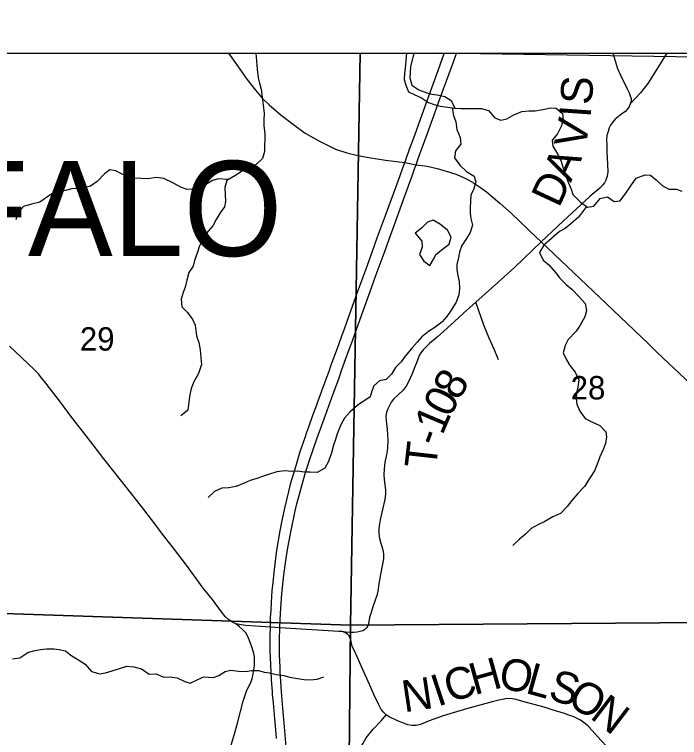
# Model space of a CAD drawing. Extents: x 0 to 34, y 0 to 22.
# Drawn here: x 6.166 to 7.359, y 16.857 to 18.153 of the extents above; entities that cross this region are included whole.
import ezdxf

# ---------------------------------------------------------------- set-up
doc = ezdxf.new("R2010")
doc.units = 0
for name, color, linetype in [('GM_X_Corporation', 7, 'Continuous'), ('GM_X_County_Road', 7, 'Continuous'), ('GM_X_County_Road_Text', 7, 'Continuous'), ('GM_X_Interstate_Route', 7, 'Continuous'), ('GM_X_Minor_Lake', 7, 'Continuous'), ('GM_X_Minor_River', 7, 'Continuous'), ('GM_X_Section_Text', 7, 'Continuous'), ('GM_X_State_Route', 7, 'Continuous'), ('GM_X_Township_Road', 7, 'Continuous'), ('GM_X_Township_Road_Text', 7, 'Continuous'), ('GM_X_Township_Text', 7, 'Continuous'), ('SH_Data', 7, 'Continuous')]:
    doc.layers.add(name, color=color, linetype=linetype)

msp = doc.modelspace()

# ---------------------------------------------------------------- linework, layer by layer
at = {"layer": 'GM_X_Corporation'}
for points in [[(6.7857, 18.0831), (6.7684, 17.0582), (5.7733, 17.0918), (5.7957, 18.0831)], [(7.8172, 18.0831), (7.7982, 17.0659), (6.7684, 17.0582), (6.7857, 18.0831)], [(7.8172, 18.0831), (7.817, 18.0695), (6.9241, 18.0832)]]:
    msp.add_lwpolyline(points, dxfattribs=at)
for points in [[(6.7684, 17.0582), (6.7585, 16.0372), (5.82, 16.0635), (5.7783, 16.0638), (5.7733, 17.0918)], [(7.7982, 17.0659), (7.8046, 16.0144), (6.8244, 16.0368), (6.7585, 16.0372), (6.7684, 17.0582)]]:
    msp.add_lwpolyline(points, close=True, dxfattribs=at)
at = {"layer": 'GM_X_County_Road'}
for points in [[(7.239, 18.0831), (7.2476, 18.0558), (7.2524, 18.0439), (7.2647, 18.0193), (7.268, 18.012), (7.2707, 18.0053), (7.2716, 18.002), (7.2719, 17.9975), (7.2703, 17.9924)], [(7.2703, 17.9924), (7.2683, 17.9874), (7.2654, 17.9836), (7.2614, 17.9791), (7.2548, 17.9744), (7.2493, 17.9701), (7.2432, 17.9649), (7.2383, 17.9593), (7.2347, 17.9541), (7.2324, 17.9493), (7.2304, 17.943), (7.2283, 17.9358), (7.2278, 17.9277), (7.2279, 17.9192), (7.2284, 17.9068), (7.2296, 17.8841), (7.2297, 17.871), (7.2285, 17.8629), (7.2266, 17.8558), (7.2239, 17.8507), (7.2205, 17.8466), (7.2156, 17.8413), (7.1985, 17.8271), (7.1501, 17.782), (7.1106, 17.7455)], [(6.7716, 17.0208), (6.7704, 17.0259), (6.7689, 17.0319), (6.7677, 17.0363), (6.7664, 17.0389), (6.764, 17.0416), (6.7596, 17.0447), (6.7534, 17.0466), (6.7478, 17.0471), (6.642, 17.0534), (6.6252, 17.0547), (6.5984, 17.0562), (6.5811, 17.0575), (6.5724, 17.0586), (6.5629, 17.0608), (6.5568, 17.0635), (6.5505, 17.0679), (6.5441, 17.0738), (6.5376, 17.0823), (6.5211, 17.1043), (6.5047, 17.1248), (6.4919, 17.142), (6.4746, 17.1659), (6.4533, 17.1936), (6.4338, 17.2183), (6.4116, 17.2479), (6.3978, 17.2657), (6.3855, 17.2818), (6.3449, 17.3328), (6.3261, 17.3566), (6.3075, 17.3814), (6.2672, 17.4331), (6.2448, 17.4624), (6.2345, 17.4763), (6.2225, 17.492), (6.2142, 17.5021), (6.209, 17.5084), (6.2015, 17.5167), (6.1575, 17.558)], [(6.5491, 16.8253), (6.5606, 16.8635), (6.5659, 16.8826), (6.5764, 16.9223), (6.5829, 16.9416), (6.5898, 16.9552), (6.5925, 16.9629), (6.5937, 16.9675), (6.5949, 16.9748), (6.5962, 16.9856), (6.5964, 16.9929), (6.5964, 17.0007), (6.5951, 17.0076), (6.5923, 17.0175), (6.5883, 17.0292), (6.5845, 17.0381), (6.5807, 17.0443), (6.5752, 17.0502), (6.5694, 17.0553), (6.5629, 17.0608)], [(7.2412, 16.8262), (7.2117, 16.8589), (7.2016, 16.8697), (7.1945, 16.8773), (7.1901, 16.8813), (7.1858, 16.8845), (7.1811, 16.8878), (7.1762, 16.8904), (7.169, 16.8938), (7.1601, 16.8972), (7.1521, 16.8998), (7.1304, 16.9066), (7.1158, 16.911), (7.0749, 16.922), (7.0659, 16.9248), (7.0583, 16.9262), (7.0496, 16.9265), (7.041, 16.9252), (7.0344, 16.9238), (7.0224, 16.9208), (6.9767, 16.908), (6.9349, 16.8958), (6.9099, 16.8866), (6.8942, 16.8803), (6.8866, 16.8784), (6.8789, 16.8782), (6.8715, 16.8798), (6.8657, 16.8817), (6.8527, 16.887), (6.838, 16.8937), (6.8325, 16.8974), (6.8275, 16.9021), (6.8237, 16.9072), (6.8186, 16.9166), (6.8109, 16.9325), (6.8031, 16.9507), (6.7947, 16.9693), (6.7804, 17.0015), (6.7749, 17.0134), (6.7718, 17.0198), (6.7716, 17.0208)]]:
    msp.add_lwpolyline(points, dxfattribs=at)
at = {"layer": 'GM_X_Interstate_Route'}
for points in [[(6.6359, 16.8552), (6.634, 16.8779), (6.6327, 16.8906), (6.6303, 16.9189), (6.6289, 16.934), (6.6285, 16.9388), (6.6269, 16.9611), (6.6255, 16.9876), (6.6247, 17.0125), (6.6247, 17.0325), (6.6248, 17.0398), (6.6252, 17.0547), (6.6254, 17.0722), (6.6261, 17.0844), (6.6268, 17.0991), (6.6282, 17.1204), (6.6292, 17.1296), (6.6321, 17.1579), (6.6366, 17.1924), (6.6425, 17.2271), (6.6463, 17.246), (6.6514, 17.2705), (6.6581, 17.2979), (6.6619, 17.3134), (6.671, 17.3446), (6.6785, 17.3693), (6.6871, 17.3948), (6.6906, 17.4043), (6.6938, 17.4135), (6.7013, 17.4343), (6.7081, 17.453), (6.7106, 17.4605), (6.7212, 17.4893), (6.7283, 17.5084), (6.7307, 17.515), (6.734, 17.5246), (6.747, 17.5597), (6.7531, 17.5768), (6.757, 17.5875), (6.7619, 17.601), (6.7751, 17.6383), (6.7814, 17.6553), (6.7965, 17.697), (6.8076, 17.7269), (6.8171, 17.7545), (6.8311, 17.7927), (6.842, 17.8219), (6.8545, 17.8558), (6.8617, 17.8758), (6.8661, 17.8874), (6.8684, 17.8939), (6.8746, 17.9114), (6.8789, 17.9236), (6.8838, 17.9366), (6.8941, 17.9652), (6.9049, 17.995), (6.9171, 18.0276), (6.9285, 18.0605), (6.9304, 18.0658), (6.9354, 18.0795), (6.9367, 18.0831)], [(6.8836, 17.876), (6.8862, 17.8835), (6.8899, 17.8944), (6.8967, 17.9124), (6.9029, 17.9299), (6.9138, 17.9596), (6.9186, 17.9728), (6.9241, 17.9882), (6.9354, 18.0194), (6.9408, 18.0339), (6.9489, 18.0567), (6.9518, 18.0645), (6.9586, 18.0831)], [(6.6544, 16.826), (6.6501, 16.8761), (6.6471, 16.9093), (6.6454, 16.9309), (6.6422, 16.9745), (6.6422, 16.9832), (6.6414, 17.0049), (6.6414, 17.032), (6.642, 17.0534), (6.6425, 17.0686), (6.6435, 17.0887), (6.6455, 17.1148), (6.6491, 17.1476), (6.6512, 17.1656), (6.6537, 17.1824), (6.6575, 17.2032), (6.662, 17.2281), (6.669, 17.2599), (6.6726, 17.2756), (6.6772, 17.2933), (6.6869, 17.3275), (6.6957, 17.3556), (6.7082, 17.392), (6.7236, 17.4343), (6.7299, 17.4511), (6.737, 17.4713), (6.7481, 17.5016), (6.7525, 17.5145), (6.7627, 17.5429), (6.7726, 17.5698), (6.7892, 17.6153), (6.8037, 17.6564), (6.8149, 17.6866), (6.8305, 17.7297), (6.8378, 17.7502), (6.8466, 17.7743), (6.8604, 17.8125), (6.8701, 17.8393), (6.8793, 17.8638), (6.8836, 17.876)]]:
    msp.add_lwpolyline(points, dxfattribs=at)
at = {"layer": 'GM_X_Minor_Lake'}
for points in [[(6.9381, 17.7355), (6.9454, 17.741), (6.9491, 17.7535), (6.9423, 17.7664), (6.9301, 17.7762), (6.9169, 17.7841), (6.9067, 17.7806), (6.8961, 17.7696), (6.8844, 17.7605)], [(6.8844, 17.7605), (6.8962, 17.7465), (6.8969, 17.7359), (6.8921, 17.7226), (6.9, 17.7109), (6.9111, 17.7026), (6.9171, 17.7132), (6.9223, 17.7231), (6.9337, 17.7322), (6.9381, 17.7355)]]:
    msp.add_lwpolyline(points, dxfattribs=at)
at = {"layer": 'GM_X_Minor_River'}
for points in [[(6.5987, 18.0831), (6.601, 18.0548), (6.603, 18.0392), (6.6057, 18.0294), (6.6083, 18.0188), (6.6095, 18.0089), (6.6111, 17.9995), (6.6122, 17.99), (6.6138, 17.9752), (6.6131, 17.9638), (6.6135, 17.9529), (6.615, 17.9396), (6.6151, 17.9282), (6.6147, 17.9187), (6.6144, 17.907), (6.611, 17.8948), (6.5993, 17.8838), (6.5883, 17.8785), (6.5766, 17.8735), (6.5611, 17.8636), (6.5471, 17.8552), (6.5434, 17.8427), (6.5438, 17.8298), (6.5442, 17.8177), (6.5427, 17.8082), (6.5352, 17.7972), (6.528, 17.7854), (6.5216, 17.774), (6.5103, 17.7607), (6.5024, 17.7485), (6.4975, 17.7364), (6.4941, 17.7265), (6.4892, 17.7117), (6.4866, 17.7019), (6.4787, 17.6901), (6.4753, 17.6768), (6.4723, 17.6643), (6.4686, 17.6544), (6.4652, 17.6426), (6.4664, 17.629), (6.4763, 17.6188), (6.4858, 17.6056), (6.49, 17.5957), (6.4923, 17.5768), (6.4969, 17.565), (6.4992, 17.5518), (6.5, 17.5374), (6.5015, 17.5253), (6.4959, 17.5093), (6.488, 17.4941), (6.4827, 17.4824), (6.4797, 17.4679), (6.479, 17.4581), (6.4768, 17.4437), (6.4647, 17.4334)], [(6.8692, 18.0831), (6.8668, 18.0568), (6.8657, 18.0474), (6.865, 18.036), (6.8681, 18.0261), (6.8726, 18.014), (6.8829, 18.0091), (6.8958, 18.0031), (6.9087, 17.9952), (6.9185, 17.9914), (6.9291, 17.9884), (6.9432, 17.9866), (6.9557, 17.9851)], [(6.882, 18.0831), (6.8763, 18.0591), (6.8756, 18.0493), (6.8752, 18.039), (6.8783, 18.0262), (6.8912, 18.0175), (6.9052, 18.0122), (6.9147, 18.01), (6.9242, 18.0085), (6.9378, 18.0055), (6.9492, 17.9984), (6.9557, 17.9851)], [(6.9511, 17.9857), (6.9534, 17.9718), (6.9576, 17.9605), (6.9592, 17.9465), (6.9653, 17.9325), (6.9664, 17.92), (6.9566, 17.9086), (6.9552, 17.8957), (6.9647, 17.8828), (6.9764, 17.8715), (6.9901, 17.8628), (6.9935, 17.8522), (6.989, 17.8389), (6.9841, 17.829), (6.9838, 17.8177), (6.9834, 17.8067), (6.9831, 17.7968), (6.9843, 17.7873), (6.9873, 17.7752), (6.9832, 17.7619), (6.9764, 17.7513), (6.9681, 17.7384), (6.964, 17.727), (6.9625, 17.7171), (6.9595, 17.7046), (6.9592, 17.6948), (6.9611, 17.6849), (6.9634, 17.6739), (6.9638, 17.6611), (6.9627, 17.6501), (6.9582, 17.6372), (6.9492, 17.6227), (6.9412, 17.6113), (6.9329, 17.6018), (6.9201, 17.5915), (6.9087, 17.5847), (6.8963, 17.5752), (6.8884, 17.5656), (6.8789, 17.5554), (6.8665, 17.5406), (6.8597, 17.5299), (6.8491, 17.52), (6.8423, 17.5083), (6.8325, 17.4984), (6.8208, 17.4964), (6.8102, 17.4869), (6.8068, 17.4774), (6.8038, 17.4676), (6.7925, 17.4599), (6.7827, 17.4535), (6.7683, 17.4405), (6.7578, 17.4295), (6.751, 17.417), (6.7446, 17.4014), (6.742, 17.3908), (6.7382, 17.3809), (6.7345, 17.3669), (6.7292, 17.3517), (6.7224, 17.3395), (6.7088, 17.3319), (6.6956, 17.3326), (6.6857, 17.3326), (6.6736, 17.3344), (6.663, 17.3336), (6.6509, 17.3347), (6.6365, 17.3328), (6.6217, 17.3282), (6.6108, 17.3247), (6.6009, 17.3213), (6.5888, 17.3178), (6.5782, 17.3125), (6.5635, 17.3068), (6.5503, 17.3044), (6.5381, 17.3036), (6.5249, 17.2979), (6.5132, 17.2869)], [(6.9557, 17.9851), (6.9666, 17.9844), (6.9928, 17.9845), (7.003, 17.9841), (7.0162, 17.9808), (7.0276, 17.9672), (7.0383, 17.9634), (7.0489, 17.9657), (7.0617, 17.9726), (7.0757, 17.9787), (7.0889, 17.9799), (7.0999, 17.9799), (7.1136, 17.9822), (7.1276, 17.9857), (7.1374, 17.9846), (7.1488, 17.9752), (7.1496, 17.9642), (7.1462, 17.9517), (7.1398, 17.9387)], [(7.1398, 17.9387), (7.1304, 17.9273), (7.1312, 17.9167), (7.1399, 17.9027), (7.1464, 17.8895), (7.1494, 17.8789), (7.1533, 17.8671), (7.1575, 17.855), (7.164, 17.8399), (7.1674, 17.8301), (7.1811, 17.8165), (7.1936, 17.8074), (7.2049, 17.8093), (7.2163, 17.823), (7.2291, 17.8261), (7.2416, 17.8174), (7.2522, 17.8186), (7.2624, 17.8323), (7.2715, 17.8456), (7.2809, 17.8592), (7.2968, 17.8654), (7.3066, 17.865), (7.3165, 17.8563), (7.3271, 17.8465), (7.3396, 17.8397), (7.3529, 17.8394), (7.3627, 17.836)], [(6.5501, 17.857), (6.5312, 17.8582), (6.5214, 17.8551), (6.5104, 17.8486), (6.4991, 17.8437), (6.4862, 17.8395), (6.4756, 17.839), (6.4654, 17.8424), (6.4502, 17.8511), (6.4339, 17.8586), (6.4203, 17.8604), (6.4055, 17.8581), (6.393, 17.8585), (6.3801, 17.8596), (6.3703, 17.8618), (6.3593, 17.8663), (6.3479, 17.8727), (6.3373, 17.8742), (6.3275, 17.8669), (6.3146, 17.8536), (6.3022, 17.8453), (6.2923, 17.8426), (6.2802, 17.841), (6.2692, 17.8402), (6.2575, 17.8371), (6.2443, 17.8359), (6.2333, 17.831), (6.2235, 17.8245), (6.2114, 17.8165), (6.1966, 17.8127), (6.1823, 17.8088), (6.1724, 17.7974), (6.1683, 17.7849)], [(7.1919, 17.8086), (7.1774, 17.7895), (7.1634, 17.7773), (7.1536, 17.7694), (7.1434, 17.7636), (7.129, 17.7511), (7.1154, 17.7393), (7.1075, 17.726), (7.114, 17.7124), (7.1242, 17.7041), (7.136, 17.6901), (7.144, 17.6802), (7.1554, 17.6689), (7.1656, 17.6602), (7.1793, 17.6462), (7.1895, 17.6345), (7.1919, 17.6224), (7.1885, 17.6106), (7.1806, 17.5958), (7.173, 17.5852), (7.1587, 17.57), (7.1534, 17.5597), (7.1501, 17.5461), (7.1558, 17.534), (7.1619, 17.5238), (7.1714, 17.5117), (7.1778, 17.4977), (7.176, 17.4848), (7.1737, 17.4749), (7.173, 17.4647), (7.1742, 17.4541), (7.1795, 17.4416), (7.1894, 17.4287), (7.2023, 17.4223), (7.2156, 17.4163), (7.2262, 17.4049), (7.2274, 17.3955), (7.2255, 17.3837), (7.2217, 17.3731), (7.2157, 17.3602), (7.212, 17.3496), (7.2063, 17.3348), (7.1984, 17.323), (7.1879, 17.3066), (7.1762, 17.2945), (7.1652, 17.2819), (7.1573, 17.2709), (7.1452, 17.2584), (7.1316, 17.2522), (7.1172, 17.2442), (7.1059, 17.2385), (7.0927, 17.2316), (7.0821, 17.2214), (7.0719, 17.2122), (7.0594, 17.2012)], [(6.1623, 16.9979), (6.1756, 16.9995), (6.1899, 17.0094), (6.2005, 17.0121), (6.213, 17.0144), (6.2236, 17.0159), (6.2365, 17.0156), (6.2463, 17.0149), (6.2577, 17.0123), (6.2672, 17.0047), (6.2797, 16.9968), (6.2926, 16.9881), (6.3044, 16.9749), (6.3191, 16.9708), (6.3294, 16.9727), (6.3415, 16.9762), (6.3547, 16.9804), (6.3676, 16.985), (6.3804, 16.9835), (6.3937, 16.9802), (6.4074, 16.9703), (6.4199, 16.9708), (6.4331, 16.9648), (6.4434, 16.9659), (6.4577, 16.9637), (6.4714, 16.9573), (6.4809, 16.9543), (6.496, 16.9616), (6.5058, 16.9654), (6.5225, 16.9643), (6.5327, 16.9678), (6.544, 16.975), (6.5543, 16.9773), (6.5679, 16.9755), (6.5804, 16.9751), (6.591, 16.9767), (6.6042, 16.9767), (6.6137, 16.9741), (6.6236, 16.9726), (6.6353, 16.9696), (6.6489, 16.9682), (6.6599, 16.9648), (6.6736, 16.9626), (6.6853, 16.9607), (6.6955, 16.96), (6.7088, 16.9616), (6.7205, 16.9658)]]:
    msp.add_lwpolyline(points, dxfattribs=at)
at = {"layer": 'GM_X_State_Route'}
msp.add_lwpolyline([(6.55, 18.0831), (6.5658, 18.0605), (6.5829, 18.037), (6.5981, 18.0168), (6.6104, 18.0028), (6.6229, 17.9908), (6.644, 17.9723), (6.6663, 17.9553), (6.6871, 17.9401), (6.7117, 17.9261), (6.7419, 17.9113), (6.7623, 17.905), (6.7791, 17.9006), (6.8012, 17.8962), (6.8316, 17.8919), (6.8661, 17.8874), (6.8862, 17.8835), (6.9058, 17.8806), (6.9239, 17.8767), (6.9344, 17.8737), (6.9459, 17.8704), (6.959, 17.8659), (6.9712, 17.8607), (6.981, 17.8557), (6.9894, 17.8509), (7.0019, 17.8429), (7.0123, 17.835), (7.0366, 17.8143), (7.0564, 17.7966), (7.1018, 17.7533), (7.1106, 17.7455), (7.2271, 17.6347), (7.3031, 17.5624), (7.3169, 17.549), (7.34, 17.5267), (7.3562, 17.5114), (7.3868, 17.4825)], dxfattribs=at)
at = {"layer": 'GM_X_Township_Road'}
for points in [[(7.3359, 18.0831), (7.3018, 18.0292), (7.2888, 18.012), (7.2703, 17.9924)], [(7.2703, 17.9924), (7.2683, 17.9874), (7.2654, 17.9836), (7.2614, 17.9791), (7.2548, 17.9744), (7.2493, 17.9701), (7.2432, 17.9649), (7.2383, 17.9593), (7.2347, 17.9541), (7.2324, 17.9493), (7.2304, 17.943), (7.2283, 17.9358), (7.2278, 17.9277), (7.2279, 17.9192), (7.2284, 17.9068), (7.2296, 17.8841), (7.2297, 17.871), (7.2285, 17.8629), (7.2266, 17.8558), (7.2239, 17.8507), (7.2205, 17.8466), (7.2156, 17.8413), (7.1985, 17.8271), (7.1501, 17.782), (7.1106, 17.7455)], [(7.1106, 17.7455), (7.063, 17.7001), (7.0329, 17.6723), (6.9935, 17.6373), (6.9713, 17.6176), (6.9545, 17.6018), (6.9237, 17.5745), (6.9105, 17.563), (6.9034, 17.5564), (6.8989, 17.5517), (6.8949, 17.5465), (6.892, 17.5414), (6.888, 17.5314), (6.8838, 17.5212), (6.879, 17.5089), (6.8728, 17.4945), (6.8684, 17.4866), (6.8631, 17.4792), (6.8544, 17.4714), (6.8457, 17.4631), (6.8418, 17.4577), (6.8393, 17.4532), (6.8357, 17.4461), (6.8333, 17.4398), (6.8321, 17.4324), (6.8324, 17.4253), (6.8345, 17.4088), (6.8354, 17.39), (6.8348, 17.376), (6.8338, 17.3664), (6.8303, 17.3501), (6.8288, 17.3377), (6.8286, 17.3282), (6.8291, 17.3191), (6.8309, 17.3056), (6.8311, 17.3002), (6.8313, 17.2939), (6.831, 17.289), (6.8301, 17.2836), (6.8257, 17.2655), (6.8217, 17.2468), (6.8199, 17.236), (6.8195, 17.2299), (6.8195, 17.2246), (6.82, 17.2173), (6.8213, 17.211), (6.8264, 17.1933), (6.8279, 17.1855), (6.828, 17.1772), (6.8225, 17.149), (6.8195, 17.1324), (6.8174, 17.119), (6.8158, 17.1112), (6.8088, 17.0908), (6.8048, 17.0789), (6.8029, 17.0719), (6.8012, 17.0644), (6.8002, 17.0584), (6.7975, 17.0535), (6.7937, 17.0499), (6.7906, 17.0483), (6.786, 17.047), (6.7805, 17.0459), (6.7746, 17.0452), (6.7672, 17.0453), (6.7605, 17.0459), (6.7534, 17.0466)], [(7.0338, 17.5335), (7.026, 17.5531), (7.0171, 17.5728), (7.0077, 17.5961), (6.9935, 17.6373)], [(6.7674, 16.6578), (6.7683, 16.7007), (6.7692, 16.7431), (6.7712, 16.7806), (6.7724, 16.7951), (6.7738, 16.8038), (6.7756, 16.8129), (6.7812, 16.829), (6.7847, 16.8357), (6.7905, 16.8457), (6.7969, 16.8562), (6.8092, 16.8717), (6.8239, 16.8876), (6.8325, 16.8974)]]:
    msp.add_lwpolyline(points, dxfattribs=at)
at = {"layer": 'SH_Data'}
msp.add_lwpolyline([(5.6652, 18.0831), (8.1124, 18.0831), (8.1124, 18.8602), (5.6652, 18.8602)], close=True, dxfattribs=at)

# ---------------------------------------------------------------- texts
at = {"layer": 'GM_X_County_Road_Text'}
for s, rotation, p in [('S', 85.4814, (7.2008, 17.9897)), ('I', 86.0486, (7.1992, 17.9666)), ('V', 79.2664, (7.1889, 17.9102)), ('A', 65.3246, (7.1635, 17.8504)), ('D', 64.9844, (7.1422, 17.8047)), ('H', 15.5481, (6.9908, 16.9326)), ('O', 349.8639, (7.0323, 16.9457)), ('L', 344.5167, (7.0802, 16.9372)), ('C', 17.0933, (6.9466, 16.919)), ('S', 343.7864, (7.121, 16.9259)), ('N', 8.4598, (6.8649, 16.9019)), ('I', 18.3232, (6.9248, 16.9118)), ('O', 329.9971, (7.1545, 16.9166)), ('N', 322.572, (7.1961, 16.8927))]:
    msp.add_text(s, height=0.0568, rotation=rotation, dxfattribs=at).set_placement(p)
at = {"layer": 'GM_X_Section_Text'}
for s, p in [('29', (6.2833, 17.5503)), ('28', (7.1633, 17.4628))]:
    msp.add_text(s, height=0.04186, rotation=0, dxfattribs=at).set_placement(p)
at = {"layer": 'GM_X_Township_Road_Text'}
for s, rotation, p in [('8', 60.3055, (6.9625, 17.4589)), ('0', 62.4993, (6.9466, 17.4283)), ('1', 66.9606, (6.9334, 17.3972)), ('-', 69.8468, (6.9257, 17.376)), ('T', 83.5926, (6.9218, 17.3372))]:
    msp.add_text(s, height=0.0568, rotation=rotation, dxfattribs=at).set_placement(p)
at = {"layer": 'GM_X_Township_Text'}
msp.add_text('BUFFALO', height=0.17045, rotation=0, dxfattribs=at).set_placement((5.5953, 17.7198))

doc.saveas('drawing.dxf')
